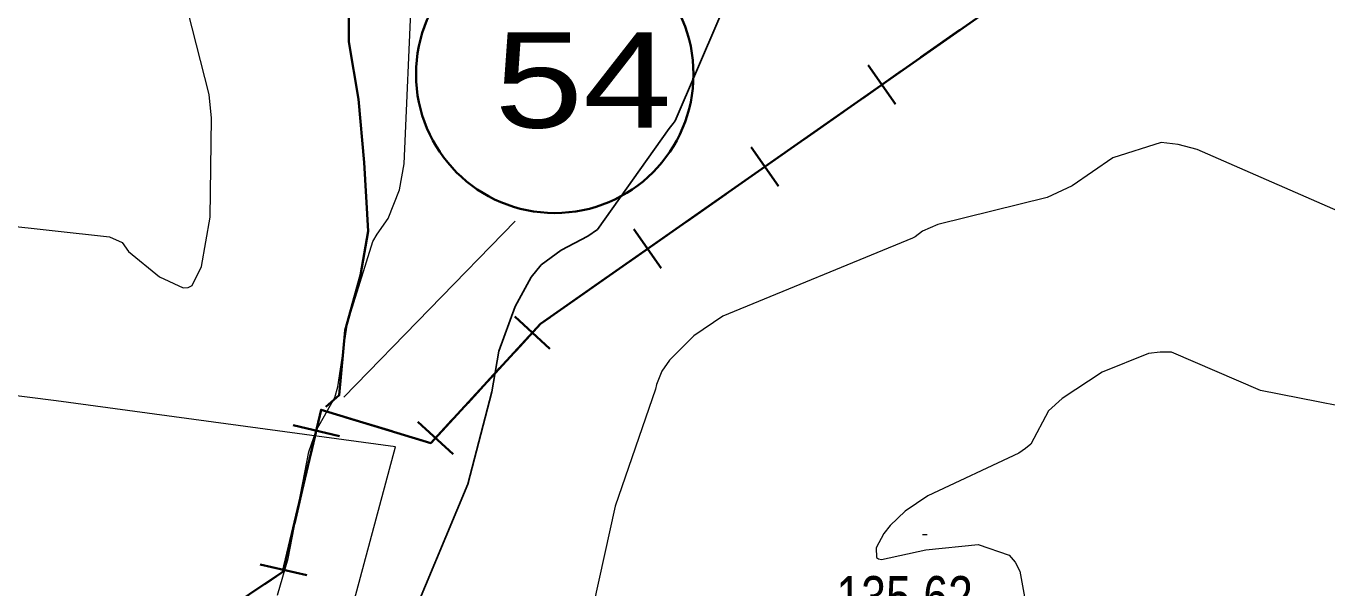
# Model space of a CAD drawing. Extents: x 483843 to 488449, y 4381269 to 4384483.
# Drawn here: x 486969.1 to 487242, y 4382813.6 to 4382931.4 of the extents above; entities that cross this region are included whole.
import ezdxf

# ---------------------------------------------------------------- set-up
doc = ezdxf.new("R2010")
doc.units = 0
doc.header["$LTSCALE"] = 3.8
for name, color, linetype, lineweight in [('13', 7, 'Continuous', 35), ('27', 7, 'Continuous', 25), ('34', 7, 'Continuous', 35), ('51', 7, 'Continuous', 13), ('6', 7, 'Continuous', 35), ('7', 7, 'Continuous', 13), ('8', 7, 'Continuous', 25), ('9', 7, 'Continuous', 13)]:
    doc.layers.add(name, color=color, linetype=linetype, lineweight=lineweight)

msp = doc.modelspace()

# ---------------------------------------------------------------- linework, layer by layer
at = {"layer": '27'}
msp.add_spline([(486286.37, 4382818.73), (486339.99, 4382829.8), (486391.37, 4382851.5), (486440.09, 4382863.84), (486483.65, 4382864.6), (486530.94, 4382876.91), (486556.13, 4382891.91), (486581.09, 4382903.76), (486654.31, 4382924.49), (486662.47, 4382925.04), (486711.17, 4382931.08), (486727.4, 4382937.04), (486766.91, 4382937.87), (486808.31, 4382909.18), (486821.81, 4382880.51), (486820.67, 4382841.64), (486812.49, 4382812.89), (486799.42, 4382770.69), (486791.78, 4382745.03), (486785, 4382714.29), (486784.58, 4382691.25), (486792.33, 4382675.66), (486812.73, 4382668.89), (486834.8, 4382649.92), (486842.09, 4382627.43), (486847.24, 4382607.13), (486841.07, 4382582.93), (486840.3, 4382544.36), (486820.33, 4382480.87), (486817.63, 4382459.06), (486815.97, 4382420.47), (486812.52, 4382387.85), (486799.99, 4382362.84), (486771.04, 4382337.85), (486733.51, 4382314.2), (486712.72, 4382296.59), (486687.38, 4382263.88), (486690.96, 4382229.15), (486713.22, 4382200.82), (486764.33, 4382192.43), (486778.5, 4382149.68), (486779.01, 4382117.89), (486787.15, 4382072.98), (486813.93, 4382065.66), (486857.54, 4382071.08), (486866.35, 4382080.34), (486893.23, 4382096.95), (486915.85, 4382116.25), (486928.06, 4382127.9), (486936.43, 4382157.7), (486928.1, 4382176.05), (486914.22, 4382205.24), (486902.98, 4382218.81), (486885.61, 4382249.79), (486879.29, 4382279.36), (486884.99, 4382315.26), (486888.52, 4382343.76), (486907.35, 4382375.88), (486922.54, 4382388.35), (486945.58, 4382366.33), (486954.28, 4382323.31), (486963.51, 4382283.6), (486982.52, 4382253.24), (487009.26, 4382225.98), (487037.6, 4382230.32), (487058.96, 4382252.37), (487069.68, 4382284.84), (487065.95, 4382338.17), (487054.24, 4382363.72), (487038.01, 4382386.56), (487027.59, 4382400.37), (487012.06, 4382422.24), (486991.9, 4382450.1), (486977.88, 4382471.56), (486976.21, 4382486.9), (486980.43, 4382521.64), (487024.88, 4382562.69), (487055.81, 4382565.06), (487106.74, 4382596.8), (487155.96, 4382614.11), (487207.74, 4382666.72), (487232.21, 4382676.6), (487267.31, 4382683.94), (487282.71, 4382693.48), (487294.56, 4382707.98), (487340.16, 4382736.84), (487389.67, 4382736.07), (487421.36, 4382716.33), (487454.29, 4382680.57), (487455.44, 4382629.06), (487501.37, 4382598.97)], degree=3, dxfattribs=at)
at = {"layer": '34'}
for p, q in [((487164.99, 4382930.63), (487156.79, 4382924.89)), ((487151.48, 4382915.06), (487145.74, 4382923.26)), ((487152.71, 4382922.03), (487144.52, 4382916.29)), ((487140.42, 4382913.42), (487132.23, 4382907.69)), ((487126.92, 4382897.86), (487121.18, 4382906.05)), ((487128.14, 4382904.82), (487119.95, 4382899.09)), ((487115.86, 4382896.22), (487107.67, 4382890.48)), ((487103.58, 4382887.62), (487095.39, 4382881.88)), ((487102.35, 4382880.65), (487096.62, 4382888.84)), ((487091.29, 4382879.01), (487083.1, 4382873.28)), ((487078.96, 4382863.75), (487071.6, 4382870.52)), ((487068.51, 4382859.77), (487061.74, 4382852.41)), ((487045.81, 4382846.49), (487036.25, 4382849.4)), ((487034.84, 4382845.47), (487025.1, 4382847.76)), ((487058.66, 4382841.68), (487051.3, 4382848.45)), ((487027.68, 4382836.88), (487025.39, 4382827.15)), ((487027.97, 4382816.28), (487018.23, 4382818.57))]:
    msp.add_line(p, q, dxfattribs=at)
for points in [[(487676.62, 4383311.4), (487577, 4383232), (487304, 4383028), (487077, 4382869), (487054, 4382844), (487031, 4382851), (487023, 4382817), (486778, 4382653), (486740, 4382634), (486629, 4382532), (486583, 4382537), (486557, 4382471), (486289, 4382313), (486283, 4382292), (486265, 4382283)], [(487079.02, 4382870.41), (487077, 4382869), (487071.9, 4382863.45)], [(487031.47, 4382850.86), (487031, 4382851), (487028.82, 4382841.75)], [(487058.36, 4382848.74), (487054, 4382844), (487050.6, 4382845.04)], [(487024.24, 4382822.29), (487023, 4382817), (487019.2, 4382814.46)]]:
    msp.add_lwpolyline(points, dxfattribs=at)
at = {"layer": '51'}
msp.add_lwpolyline([(486960.5, 4382614.18), (486990.67, 4382635.03), (487046.62, 4382843.21), (486975.39, 4382852.9), (486875.9, 4382865.44)], dxfattribs=at)
at = {"layer": '6', "lineweight": 25}
msp.add_line((487035.77, 4382853.6), (487071.7, 4382890.56), dxfattribs=at)
at = {"layer": '6'}
msp.add_lwpolyline([(487036.82, 4382939.39), (487036.82, 4382928.15), (487038.83, 4382916.11), (487040.03, 4382902.87), (487040.84, 4382888.42), (487039.23, 4382879.18), (487036.02, 4382867.67), (487034.81, 4382854.02), (487032, 4382851.61)], dxfattribs=at)
msp.add_circle((487080, 4382921.34), 29.1, dxfattribs=at)
at = {"layer": '7'}
msp.add_line((487157.13, 4382824.83), (487158.13, 4382824.83), dxfattribs=at)
at = {"layer": '8'}
msp.add_lwpolyline([(487260.36, 4382967.81), (487212.72, 4382975.13), (487201.34, 4382975.14), (487181.54, 4382972.94), (487144.39, 4382963.7), (487131.82, 4382958.07), (487126.47, 4382954.43), (487121.9, 4382948.76), (487119.1, 4382943.88), (487105.25, 4382911.6), (487104.87, 4382911.01), (487103.97, 4382909.97), (487088.94, 4382888.78), (487086.91, 4382887.36), (487081.37, 4382884.48), (487077.14, 4382881.38), (487075.04, 4382878.81), (487071.68, 4382872.63), (487068.24, 4382863.27), (487066.83, 4382854.75), (487061.76, 4382835.38), (487048.26, 4382803.13)], dxfattribs=at)
at = {"layer": '9'}
for points in [[(487021.84, 4382812.15), (487024.11, 4382819.8), (487028.41, 4382842.18), (487030.06, 4382846.77), (487030.49, 4382847.65), (487033.88, 4382853.59), (487034.52, 4382855.83), (487036.52, 4382869.21), (487041.86, 4382886.24), (487042.74, 4382887.83), (487045.07, 4382891.12), (487047.45, 4382897.13), (487048.39, 4382902.56), (487050.05, 4382939.28), (487050.54, 4382940.43), (487055.79, 4382948.29), (487062.37, 4382955.89), (487080.93, 4382972.77), (487084.46, 4382974.49), (487148.25, 4382990.07), (487157.42, 4382990.91), (487210.77, 4382989.23), (487247.1, 4382991.34)], [(486951.73, 4382891.1), (486986.58, 4382887.26), (486989.3, 4382886.04), (486990.59, 4382884.16), (486997.08, 4382878.86), (487002.05, 4382876.54), (487003.08, 4382876.62), (487003.97, 4382877.02), (487005.94, 4382881.04), (487007.73, 4382891.35), (487008, 4382912.16), (487007.49, 4382917.11), (487003.05, 4382934.63)], [(487248.82, 4382890.7), (487214.73, 4382905.59), (487210.79, 4382906.58), (487207.2, 4382907.01), (487197.07, 4382903.84), (487188.55, 4382897.94), (487183.3, 4382895.5), (487160.32, 4382889.85), (487157.15, 4382888.44), (487155.59, 4382887.25), (487155.04, 4382886.95), (487115.25, 4382870.62), (487109.18, 4382866.5), (487104.05, 4382861.41), (487102.49, 4382859.08), (487101.35, 4382856.29), (487101.15, 4382855.32)], [(487284.92, 4382843.85), (487228.05, 4382855.02), (487209.35, 4382863.04), (487207, 4382863.09), (487204.55, 4382862.8), (487194.82, 4382858.91), (487186.45, 4382853.37), (487183.58, 4382850.8), (487179.85, 4382843.78), (487178.72, 4382842.84), (487177.32, 4382841.89), (487158.28, 4382832.94), (487153.51, 4382829.76), (487150.33, 4382826.71), (487149, 4382825.05), (487147.39, 4382822.07), (487147.48, 4382820), (487147.92, 4382819.75), (487148.54, 4382819.62), (487157.84, 4382821.66), (487168.81, 4382822.74), (487175.29, 4382820.54), (487176.55, 4382819.04), (487177.58, 4382817.16), (487179.35, 4382807.14)], [(487101.15, 4382855.32), (487092.68, 4382830.79), (487087.03, 4382805.1)]]:
    msp.add_lwpolyline(points, dxfattribs=at)

# ---------------------------------------------------------------- texts
at = {"layer": '13', "width": 1.25}
msp.add_text('54', height=20, dxfattribs=at).set_placement((487067.35, 4382910.13))
at = {"layer": '7', "width": 0.8}
msp.add_text('135,62', height=8.75, dxfattribs=at).set_placement((487139.07, 4382807.37))

doc.saveas('drawing.dxf')
